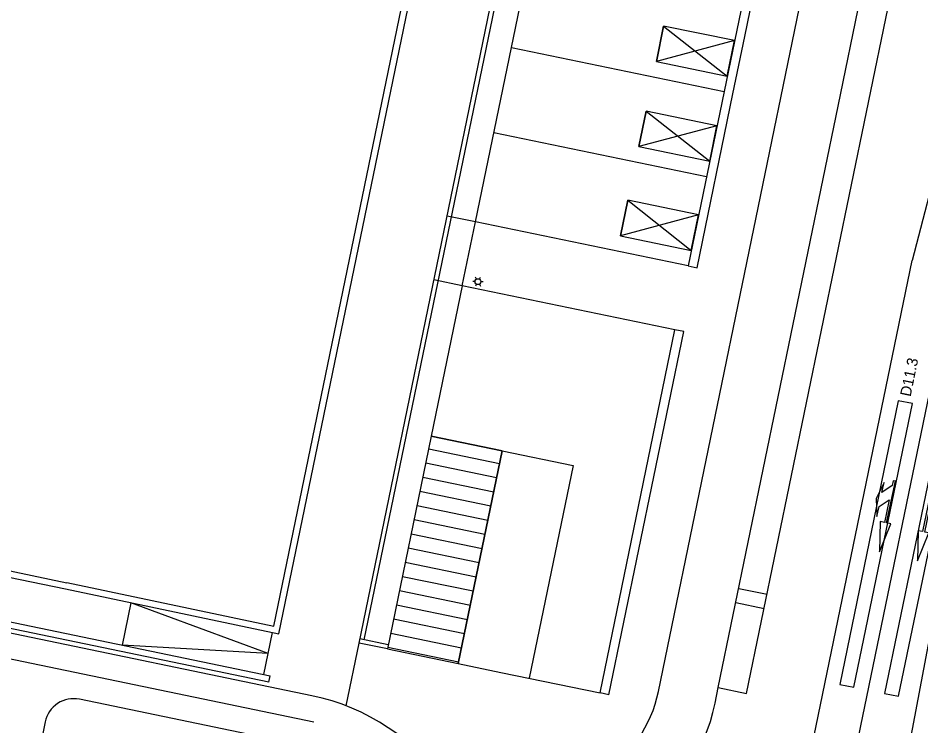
# Model space of a CAD drawing. Extents: x 81065 to 81486, y 452384 to 452681.
# Drawn here: x 81170.8 to 81233.1, y 452572 to 452620.9 of the extents above; entities that cross this region are included whole.
import ezdxf

# ---------------------------------------------------------------- set-up
doc = ezdxf.new("R2010")
doc.units = 0
for name, color, linetype in [('B-BH-IE-MEUBILAIR_WEGMEUBILAIR_LICHTMAST-S', 7, 'Continuous'), ('B-BH-OG-TOPOGRAFIE_BEBOUWING-GV', 7, 'Continuous'), ('B-BH-OG-TOPOGRAFIE_BEBOUWING_PANDSCHEIDING-GV', 7, 'Continuous'), ('B-BH-VH-KANTOPSLUITING-GV', 7, 'Continuous'), ('B-WE-VW-MARKERING_LANGS_STREEP_13_010-G', 7, 'Continuous'), ('B-WE-VW-MARKERING_LANGS_STREEP_13_030-G', 7, 'Continuous'), ('B-WE-VW-MARKERING_LANGS_STREEP_30270_010-G', 7, 'Continuous'), ('B-WE-VW-MARKERING_PIJL-S', 7, 'Continuous'), ('N-OI-KL-VRI_LUS_DETECTIE-G', 7, 'Continuous'), ('N-OI-KL-VRI_LUS_DETECTIE-T18', 7, 'Continuous')]:
    doc.layers.add(name, color=color, linetype=linetype)

msp = doc.modelspace()

# ---------------------------------------------------------------- linework, layer by layer
at = {"layer": 'B-BH-IE-MEUBILAIR_WEGMEUBILAIR_LICHTMAST-S'}
for p, q in [((81202.329, 452602.684), (81202.179, 452602.684)), ((81202.429, 452602.857), (81202.354, 452602.987)), ((81202.429, 452602.511), (81202.354, 452602.381)), ((81202.629, 452602.857), (81202.704, 452602.987)), ((81202.629, 452602.511), (81202.704, 452602.381)), ((81202.729, 452602.684), (81202.879, 452602.684))]:
    msp.add_line(p, q, dxfattribs=at)
msp.add_circle((81202.529, 452602.684), 0.2, dxfattribs=at)
at = {"layer": 'B-BH-OG-TOPOGRAFIE_BEBOUWING-GV'}
for p, q in [((81201.448, 452602.397), (81199.306, 452592.015)), ((81216.139, 452599.365), (81201.448, 452602.397)), ((81210.965, 452574.293), (81216.139, 452599.365)), ((81199.306, 452592.015), (81209.099, 452589.995)), ((81204.203, 452591.005), (81201.171, 452576.315)), ((81209.099, 452589.995), (81206.068, 452575.304)), ((81201.171, 452576.315), (81204.109, 452575.708)), ((81204.109, 452575.708), (81210.965, 452574.293))]:
    msp.add_line(p, q, dxfattribs=at)
msp.add_lwpolyline([(81202.358, 452606.804), (81210.967, 452648.525), (81225.658, 452645.493), (81217.048, 452603.772)], close=True, dxfattribs=at)
at = {"layer": 'B-BH-OG-TOPOGRAFIE_BEBOUWING_PANDSCHEIDING-GV'}
for p, q in [((81204.841, 452618.85), (81219.534, 452615.819)), ((81203.631, 452612.974), (81218.321, 452609.942))]:
    msp.add_line(p, q, dxfattribs=at)
for points in [[(81219.753, 452616.879), (81220.258, 452619.327), (81215.361, 452620.337), (81214.856, 452617.889)], [(81215.361, 452620.337), (81219.753, 452616.879), (81220.258, 452619.327), (81214.856, 452617.889)], [(81218.54, 452611.002), (81219.046, 452613.451), (81214.149, 452614.461), (81213.644, 452612.013)], [(81214.149, 452614.461), (81218.54, 452611.002), (81219.046, 452613.451), (81213.644, 452612.013)], [(81212.878, 452608.304), (81217.27, 452604.845), (81217.775, 452607.293), (81212.373, 452605.856)], [(81217.27, 452604.845), (81217.775, 452607.293), (81212.878, 452608.304), (81212.373, 452605.856)]]:
    msp.add_lwpolyline(points, close=True, dxfattribs=at)
at = {"layer": 'B-BH-VH-KANTOPSLUITING-GV'}
for p, q in [((81214.996, 452574.379), (81235.869, 452675.532)), ((81227.422, 452614.804), (81239.953, 452675.532)), ((81229.381, 452614.399), (81241.995, 452675.532)), ((81188.429, 452578.889), (81203.132, 452650.139)), ((81188.771, 452578.367), (81203.561, 452650.044)), ((81194.316, 452577.73), (81208.993, 452648.853)), ((81194.671, 452577.963), (81209.286, 452648.788)), ((81220.96, 452619.61), (81226.275, 452645.366)), ((81238.809, 452628.384), (81232.532, 452604.152)), ((81219.136, 452574.65), (81227.422, 452614.804)), ((81221.095, 452574.245), (81229.381, 452614.399)), ((81202.358, 452606.804), (81200.399, 452607.208)), ((81201.448, 452602.397), (81202.358, 452606.804)), ((81217.048, 452603.772), (81217.665, 452603.645)), ((81221.337, 452549.903), (81232.532, 452604.152)), ((81201.448, 452602.397), (81199.49, 452602.801)), ((81211.582, 452574.166), (81216.756, 452599.238)), ((81199.306, 452592.015), (81196.275, 452577.325)), ((81191.051, 452574.095), (81109.887, 452590.909)), ((81199.128, 452591.15), (81204.024, 452590.14)), ((81198.926, 452590.171), (81203.822, 452589.161)), ((81198.724, 452589.192), (81203.62, 452588.181)), ((81198.521, 452588.212), (81203.418, 452587.202)), ((81149.134, 452587.072), (81174.124, 452581.9)), ((81198.319, 452587.233), (81203.216, 452586.223)), ((81148.615, 452586.73), (81174.035, 452581.469)), ((81198.117, 452586.254), (81203.014, 452585.243)), ((81197.915, 452585.274), (81202.811, 452584.264)), ((81148.005, 452583.789), (81188.17, 452575.468)), ((81197.713, 452584.295), (81202.609, 452583.284)), ((81188.081, 452575.038), (81147.916, 452583.358)), ((81197.511, 452583.315), (81202.407, 452582.305)), ((81174.124, 452581.901), (81188.429, 452578.889)), ((81197.309, 452582.336), (81202.205, 452581.326)), ((81174.034, 452581.47), (81188.771, 452578.367)), ((81197.107, 452581.357), (81202.003, 452580.346)), ((81220.551, 452581.505), (81222.509, 452581.101)), ((81178.551, 452580.519), (81177.943, 452577.587)), ((81188.041, 452577.008), (81178.551, 452580.519)), ((81196.905, 452580.377), (81201.801, 452579.367)), ((81220.349, 452580.526), (81222.307, 452580.122)), ((81196.703, 452579.398), (81201.599, 452578.388)), ((81187.741, 452575.557), (81188.34, 452578.458)), ((81196.5, 452578.419), (81201.397, 452577.408)), ((81188.041, 452577.008), (81177.944, 452577.59)), ((81193.422, 452573.396), (81194.316, 452577.73)), ((81196.275, 452577.325), (81194.316, 452577.73)), ((81196.336, 452577.619), (81194.377, 452578.023)), ((81196.298, 452577.439), (81201.195, 452576.429)), ((81188.081, 452575.038), (81188.17, 452575.468)), ((81218.913, 452573.571), (81219.136, 452574.65)), ((81219.136, 452574.65), (81221.095, 452574.245)), ((81188.957, 452570.955), (81174.992, 452573.848)), ((81211.582, 452574.166), (81210.965, 452574.293)), ((81172.628, 452572.294), (81172.146, 452569.962))]:
    msp.add_line(p, q, dxfattribs=at)
for points in [[(81217.665, 452603.645), (81220.141, 452615.644), (81220.96, 452619.61)], [(81216.756, 452599.238), (81216.139, 452599.365), (81216.139, 452599.365)]]:
    msp.add_lwpolyline(points, dxfattribs=at)
for points in [[(81196.275, 452577.325), (81201.171, 452576.315), (81204.203, 452591.005), (81199.306, 452592.015)], [(81199.306, 452592.015), (81196.275, 452577.325), (81201.171, 452576.315), (81204.203, 452591.005)]]:
    msp.add_lwpolyline(points, close=True, dxfattribs=at)
for centre, radius, start, end in [((81206.182, 452576.198), 9, 302.80792, 348.34046), ((81174.586, 452571.889), 2, 78.2967, 168.32655), ((81188.008, 452559.407), 15, 34.31134, 78.2967), ((81206.182, 452576.198), 13, 302.80792, 348.34046)]:
    msp.add_arc(centre, radius, start, end, dxfattribs=at)
at = {"layer": 'B-WE-VW-MARKERING_LANGS_STREEP_13_010-G'}
msp.add_line((81234.813, 452600.381), (81225.36, 452554.492), dxfattribs=at)
at = {"layer": 'B-WE-VW-MARKERING_LANGS_STREEP_13_030-G'}
msp.add_line((81231.691, 452567.281), (81238.216, 452601.793), dxfattribs=at)
at = {"layer": 'B-WE-VW-MARKERING_LANGS_STREEP_30270_010-G'}
msp.add_line((81191.195, 452572.279), (81109.532, 452589.195), dxfattribs=at)
at = {"layer": 'B-WE-VW-MARKERING_PIJL-S'}
for p, q in [((81230.588, 452588.819), (81230.049, 452587.706)), ((81230.445, 452588.134), (81230.588, 452588.819)), ((81230.77, 452586.023), (81231.373, 452588.911)), ((81231.227, 452588.941), (81231.155, 452588.599)), ((81231.373, 452588.911), (81231.227, 452588.941)), ((81231.155, 452588.599), (81230.445, 452588.134)), ((81230.049, 452587.706), (81230.098, 452586.47)), ((81230.241, 452587.155), (81230.951, 452587.62)), ((81230.951, 452587.62), (81230.624, 452586.054)), ((81230.098, 452586.47), (81230.241, 452587.155)), ((81230.33, 452586.115), (81230.278, 452584.032)), ((81230.278, 452584.032), (81231.064, 452585.962)), ((81230.624, 452586.054), (81230.33, 452586.115)), ((81231.064, 452585.962), (81230.77, 452586.023))]:
    msp.add_line(p, q, dxfattribs=at)
msp.add_lwpolyline([(81232.905, 452583.4), (81233.691, 452585.33), (81233.397, 452585.392), (81234, 452588.279), (81233.853, 452588.31), (81233.25, 452585.422), (81232.957, 452585.484)], close=True, dxfattribs=at)
at = {"layer": 'N-OI-KL-VRI_LUS_DETECTIE-G'}
for p, q in [((81231.569, 452594.464), (81227.529, 452574.877)), ((81232.549, 452594.263), (81231.569, 452594.464)), ((81228.507, 452574.675), (81232.549, 452594.263)), ((81234.661, 452593.841), (81230.621, 452574.254)), ((81231.599, 452574.052), (81235.641, 452593.64)), ((81227.529, 452574.877), (81228.507, 452574.675)), ((81230.621, 452574.254), (81231.599, 452574.052))]:
    msp.add_line(p, q, dxfattribs=at)

# ---------------------------------------------------------------- texts
at = {"layer": 'N-OI-KL-VRI_LUS_DETECTIE-T18'}
msp.add_text('D11.3', height=0.75, rotation=78.39173, dxfattribs=at).set_placement((81232.422, 452594.709))

doc.saveas('drawing.dxf')
